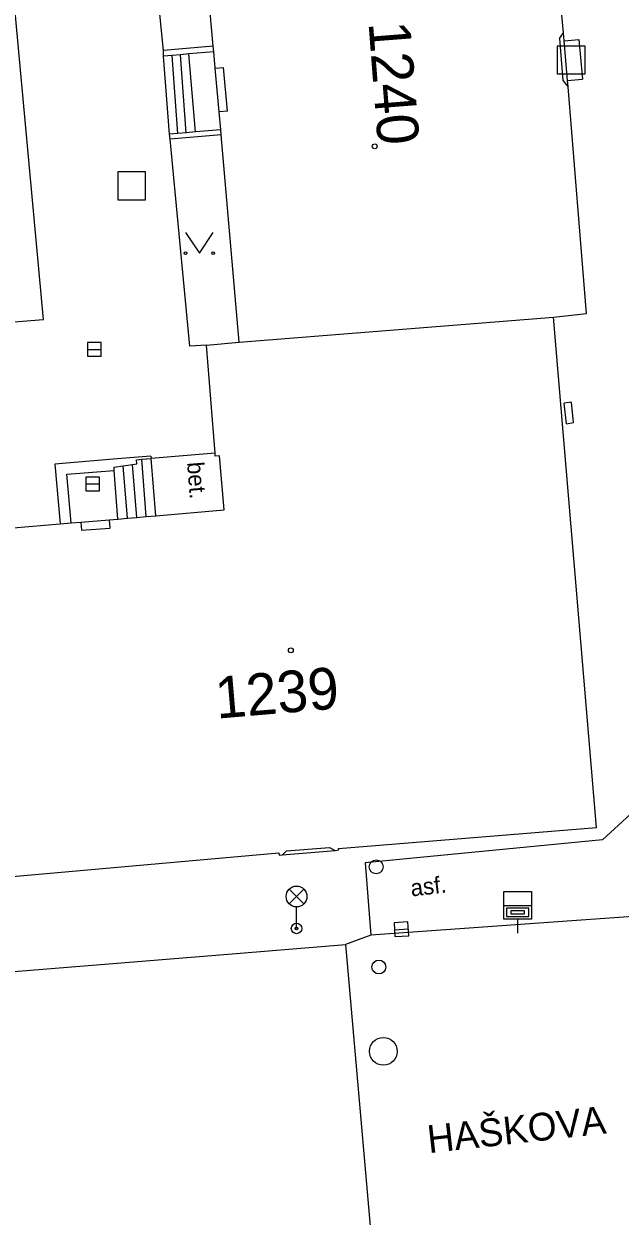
# Model space of a CAD drawing. Extents: x -642282 to -641982, y -1041678 to -1041427.
# Drawn here: x -642224.25 to -642202.75, y -1041576.77 to -1041533.81 of the extents above; entities that cross this region are included whole.
import ezdxf

# ---------------------------------------------------------------- set-up
doc = ezdxf.new("R2010")
doc.units = 0
for name, color, linetype in [('Budovy', 7, 'Continuous'), ('Popis povrchů', 7, 'Continuous'), ('Popis ulice', 7, 'Continuous'), ('Popis ČP_ ČE', 7, 'Continuous'), ('Pris-HUP', 7, 'Continuous'), ('Rozhraní ploch 1', 7, 'Continuous'), ('Rozhraní ploch 2', 7, 'Continuous'), ('Znaky doprava', 7, 'Continuous'), ('Znaky kanalizace', 7, 'Continuous'), ('Znaky plyn', 7, 'Continuous'), ('Znaky voda', 7, 'Continuous'), ('Značky KM', 7, 'Continuous'), ('Značky předmětů', 7, 'Continuous'), ('Šachty ner_', 7, 'Continuous')]:
    doc.layers.add(name, color=color, linetype=linetype)

msp = doc.modelspace()

# ---------------------------------------------------------------- linework, layer by layer
at = {"layer": 'Budovy'}
for p, q in [((-642204.8, -1041534.14), (-642205.513, -1041526.125)), ((-642217.42, -1041534.621), (-642218.078, -1041527.179)), ((-642204.94, -1041534.34), (-642204.8, -1041534.14)), ((-642204.94, -1041534.34), (-642204.82, -1041535.86)), ((-642204.775, -1041534.427), (-642204.8, -1041534.14)), ((-642204.65, -1041535.857), (-642204.775, -1041534.427)), ((-642217.402, -1041534.82), (-642217.42, -1041534.621)), ((-642217.35, -1041535.41), (-642217.402, -1041534.82)), ((-642217.35, -1041535.41), (-642217.051, -1041535.384)), ((-642217.21, -1041536.99), (-642217.35, -1041535.41)), ((-642216.911, -1041536.964), (-642217.051, -1041535.384)), ((-642204.82, -1041535.86), (-642204.63, -1041536.08)), ((-642204.63, -1041536.08), (-642204.65, -1041535.857)), ((-642203.97, -1041544.25), (-642204.63, -1041536.08)), ((-642216.911, -1041536.964), (-642217.21, -1041536.99)), ((-642217.154, -1041537.63), (-642217.21, -1041536.99)), ((-642217.139, -1041537.811), (-642217.154, -1041537.63)), ((-642216.49, -1041545.28), (-642217.139, -1041537.811)), ((-642205.16, -1041544.38), (-642203.97, -1041544.25)), ((-642216.49, -1041545.28), (-642205.16, -1041544.38)), ((-642203.61, -1041562.76), (-642205.16, -1041544.38)), ((-642217.67, -1041545.39), (-642216.49, -1041545.28)), ((-642217.358, -1041549.277), (-642217.67, -1041545.39)), ((-642217.348, -1041549.393), (-642217.358, -1041549.277)), ((-642217.199, -1041549.38), (-642217.348, -1041549.393)), ((-642217.03, -1041551.32), (-642217.199, -1041549.38)), ((-642221.17, -1041551.68), (-642220.86, -1041551.653)), ((-642220.86, -1041551.653), (-642220.519, -1041551.623)), ((-642220.519, -1041551.623), (-642220.177, -1041551.593)), ((-642220.177, -1041551.593), (-642219.837, -1041551.563)), ((-642219.837, -1041551.563), (-642219.495, -1041551.534)), ((-642219.495, -1041551.534), (-642217.03, -1041551.32)), ((-642227.82, -1041552.25), (-642222.939, -1041551.824)), ((-642222.939, -1041551.824), (-642222.541, -1041551.79)), ((-642222.541, -1041551.79), (-642222.2, -1041551.76)), ((-642222.2, -1041551.76), (-642221.17, -1041551.68)), ((-642222.2, -1041551.76), (-642222.177, -1041552.059)), ((-642222.177, -1041552.059), (-642221.147, -1041551.979)), ((-642221.17, -1041551.68), (-642221.147, -1041551.979)), ((-642212.905, -1041563.517), (-642203.61, -1041562.76)), ((-642226.67, -1041564.71), (-642215.057, -1041563.683)), ((-642215.057, -1041563.683), (-642215.05, -1041563.759)), ((-642214.93, -1041563.75), (-642213.03, -1041563.59)), ((-642214.93, -1041563.75), (-642214.78, -1041563.61)), ((-642214.78, -1041563.61), (-642213.23, -1041563.48)), ((-642213.23, -1041563.48), (-642213.03, -1041563.59)), ((-642213.03, -1041563.59), (-642212.899, -1041563.573)), ((-642212.899, -1041563.573), (-642212.905, -1041563.517)), ((-642215.05, -1041563.759), (-642214.93, -1041563.75))]:
    msp.add_line(p, q, dxfattribs=at)
at = {"layer": 'Pris-HUP'}
for p, q in [((-642204.51, -1041547.44), (-642204.77, -1041547.48)), ((-642204.69, -1041548.22), (-642204.77, -1041547.48)), ((-642204.43, -1041548.18), (-642204.51, -1041547.44)), ((-642204.69, -1041548.22), (-642204.43, -1041548.18))]:
    msp.add_line(p, q, dxfattribs=at)
at = {"layer": 'Rozhraní ploch 1'}
for p, q in [((-642219.22, -1041534.78), (-642220.29, -1041523.64)), ((-642223.54, -1041544.46), (-642225.41, -1041524.17)), ((-642218.27, -1041545.43), (-642218.97, -1041537.97)), ((-642236.736, -1041545.531), (-642223.54, -1041544.46)), ((-642217.67, -1041545.39), (-642218.27, -1041545.43)), ((-642221.033, -1041549.501), (-642223.135, -1041549.674)), ((-642219.667, -1041549.389), (-642221.033, -1041549.501)), ((-642220.18, -1041549.67), (-642220.19, -1041549.52)), ((-642219.667, -1041549.389), (-642219.66, -1041549.47)), ((-642223.135, -1041549.674), (-642222.939, -1041551.824)), ((-642222.7, -1041550.04), (-642221, -1041549.9)), ((-642221, -1041549.9), (-642220.99, -1041549.78)), ((-642222.541, -1041551.79), (-642222.7, -1041550.04)), ((-642217.327, -1041567.358), (-642212.65, -1041566.98)), ((-642237.538, -1041568.993), (-642217.327, -1041567.358))]:
    msp.add_line(p, q, dxfattribs=at)
for points in [[(-642220.19, -1041549.52), (-642220.001, -1041549.502), (-642219.66, -1041549.47)], [(-642220.99, -1041549.78), (-642220.67, -1041549.737), (-642220.329, -1041549.69), (-642220.18, -1041549.67)], [(-642195.89, -1041565.52), (-642211.74, -1041566.64)], [(-642211.74, -1041566.64), (-642212.65, -1041566.98)]]:
    msp.add_lwpolyline(points, dxfattribs=at)
at = {"layer": 'Rozhraní ploch 2'}
for p, q in [((-642204.775, -1041534.427), (-642204.24, -1041534.38)), ((-642204.24, -1041534.38), (-642204.11, -1041535.81)), ((-642217.42, -1041534.621), (-642219.22, -1041534.78)), ((-642219.21, -1041534.98), (-642219.22, -1041534.78)), ((-642218.057, -1041537.709), (-642218.301, -1041534.899)), ((-642219, -1041537.79), (-642219.21, -1041534.98)), ((-642218.697, -1041537.764), (-642218.907, -1041534.953)), ((-642218.394, -1041537.738), (-642218.604, -1041534.926)), ((-642204.65, -1041535.857), (-642204.11, -1041535.81)), ((-642218.97, -1041537.97), (-642219, -1041537.79)), ((-642217.139, -1041537.811), (-642218.97, -1041537.97)), ((-642219.837, -1041551.563), (-642220.001, -1041549.502)), ((-642217.358, -1041549.277), (-642219.66, -1041549.47)), ((-642219.495, -1041551.534), (-642219.66, -1041549.47)), ((-642220.86, -1041551.653), (-642221, -1041549.9)), ((-642220.519, -1041551.623), (-642220.67, -1041549.737)), ((-642220.177, -1041551.593), (-642220.329, -1041549.69)), ((-642197.01, -1041557.36), (-642203.39, -1041563.21)), ((-642203.39, -1041563.21), (-642211.95, -1041564.04)), ((-642211.95, -1041564.04), (-642211.74, -1041566.64))]:
    msp.add_line(p, q, dxfattribs=at)
for points in [[(-642217.402, -1041534.82), (-642218.301, -1041534.899), (-642218.604, -1041534.926), (-642218.907, -1041534.953), (-642219.21, -1041534.98)], [(-642217.154, -1041537.63), (-642218.057, -1041537.709), (-642218.394, -1041537.738), (-642218.697, -1041537.764), (-642219, -1041537.79)], [(-642212.65, -1041566.98), (-642212.04, -1041573.97)], [(-642212.04, -1041573.97), (-642211.41, -1041581.24)]]:
    msp.add_lwpolyline(points, dxfattribs=at)
at = {"layer": 'Znaky doprava'}
for p, q in [((-642214.685, -1041564.985), (-642214.155, -1041565.515)), ((-642214.685, -1041565.515), (-642214.155, -1041564.985)), ((-642214.42, -1041566.4), (-642214.42, -1041565.625))]:
    msp.add_line(p, q, dxfattribs=at)
for centre, radius in [((-642214.42, -1041565.25), 0.375), ((-642214.42, -1041566.4), 0.19), ((-642214.42, -1041566.4), 0.05)]:
    msp.add_circle(centre, radius, dxfattribs=at)
at = {"layer": 'Znaky kanalizace'}
for p, q in [((-642221.96, -1041545.54), (-642221.46, -1041545.54)), ((-642222.02, -1041550.39), (-642221.52, -1041550.39)), ((-642210.889, -1041566.446), (-642210.391, -1041566.414))]:
    msp.add_line(p, q, dxfattribs=at)
for points in [[(-642221.96, -1041545.79), (-642221.46, -1041545.79), (-642221.46, -1041545.29), (-642221.96, -1041545.29)], [(-642222.02, -1041550.64), (-642221.52, -1041550.64), (-642221.52, -1041550.14), (-642222.02, -1041550.14)], [(-642210.873, -1041566.696), (-642210.374, -1041566.663), (-642210.407, -1041566.164), (-642210.906, -1041566.197)]]:
    msp.add_lwpolyline(points, close=True, dxfattribs=at)
msp.add_circle((-642211.29, -1041570.83), 0.5, dxfattribs=at)
at = {"layer": 'Znaky plyn'}
msp.add_circle((-642211.55, -1041564.18), 0.25, dxfattribs=at)
at = {"layer": 'Znaky voda'}
msp.add_line((-642206.45, -1041566.07), (-642206.45, -1041566.57), dxfattribs=at)
for points in [[(-642206.95, -1041565.57), (-642206.95, -1041565.07), (-642205.95, -1041565.07), (-642205.95, -1041565.57)], [(-642205.95, -1041565.57), (-642205.95, -1041566.07), (-642206.95, -1041566.07), (-642206.95, -1041565.57), (-642205.95, -1041565.57)]]:
    msp.add_lwpolyline(points, dxfattribs=at)
for points in [[(-642206.85, -1041565.97), (-642206.05, -1041565.97), (-642206.05, -1041565.67), (-642206.85, -1041565.67)], [(-642206.7, -1041565.87), (-642206.2, -1041565.87), (-642206.2, -1041565.77), (-642206.7, -1041565.77)]]:
    msp.add_lwpolyline(points, close=True, dxfattribs=at)
msp.add_circle((-642211.45, -1041567.79), 0.25, dxfattribs=at)
at = {"layer": 'Značky KM'}
for p, q in [((-642218.424, -1041541.329), (-642217.924, -1041542.079)), ((-642217.924, -1041542.079), (-642217.424, -1041541.329))]:
    msp.add_line(p, q, dxfattribs=at)
for centre in [(-642218.424, -1041542.079), (-642217.424, -1041542.079)]:
    msp.add_circle(centre, 0.05, dxfattribs=at)
at = {"layer": 'Značky předmětů'}
for centre in [(-642211.6, -1041538.229), (-642214.625, -1041556.384)]:
    msp.add_circle(centre, 0.0875, dxfattribs=at)
at = {"layer": 'Šachty ner_'}
for points in [[(-642205.02, -1041535.62), (-642204.02, -1041535.62), (-642204.02, -1041534.62), (-642205.02, -1041534.62)], [(-642220.86, -1041540.15), (-642219.86, -1041540.15), (-642219.86, -1041539.15), (-642220.86, -1041539.15)]]:
    msp.add_lwpolyline(points, close=True, dxfattribs=at)

# ---------------------------------------------------------------- texts
at = {"layer": 'Popis povrchů'}
for s, rotation, p in [('bet.', 274.5706, (-642218.368, -1041549.616)), ('asf.', 6.5477, (-642210.275, -1041565.25))]:
    msp.add_text(s, height=0.6, rotation=rotation, dxfattribs=at).set_placement(p)
at = {"layer": 'Popis ulice'}
msp.add_text('HAŠKOVA', height=1, rotation=6.3457, dxfattribs=at).set_placement((-642209.65, -1041574.498))
at = {"layer": 'Popis ČP_ ČE'}
for s, rotation, p in [('1240', 274.458, (-642211.827, -1041533.776)), ('1239', 4.86, (-642217.289, -1041558.845))]:
    msp.add_text(s, height=1.5, rotation=rotation, dxfattribs=at).set_placement(p)

doc.saveas('drawing.dxf')
